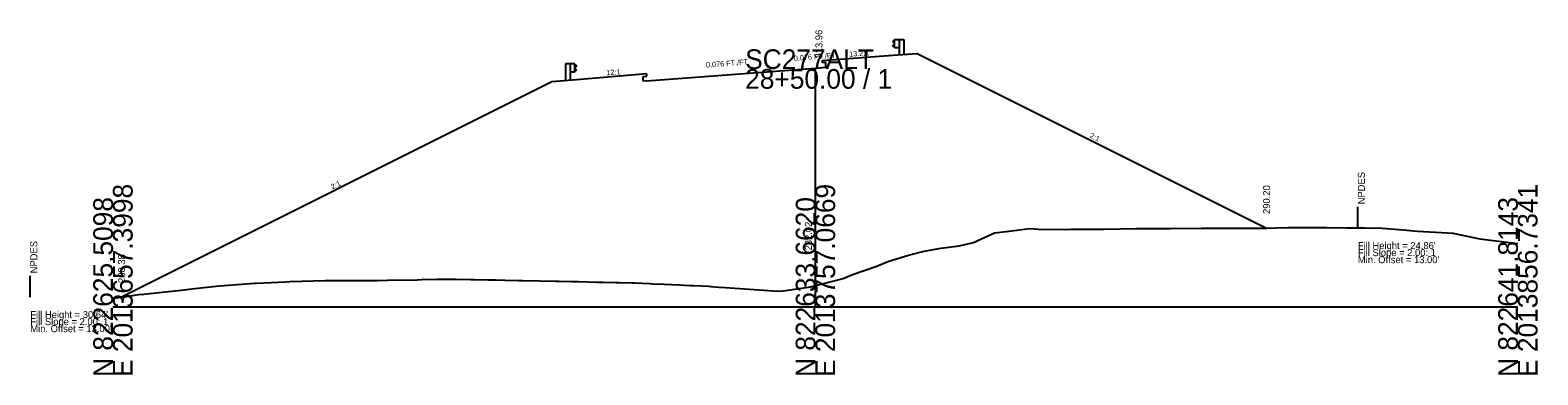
# Model space of a CAD drawing. Extents: x 205929 to 2357175, y -1785700 to 827636.
# Drawn here: x 2017408.4 to 2017623, y 826534.6 to 826583.6 of the extents above; entities that cross this region are included whole.
import ezdxf

# ---------------------------------------------------------------- set-up
doc = ezdxf.new("R2010")
doc.units = 0
for name, color, linetype in [('RD_GPK_XS_Cell', 7, 'Continuous'), ('RD_XS_Base', 7, 'Continuous'), ('RD_XS_EarthShd', 7, 'Continuous'), ('RD_XS_ExGround', 7, 'Continuous'), ('RD_XS_GR', 7, 'Continuous'), ('RD_XS_NPDES', 7, 'Continuous'), ('RD_XS_Pave', 7, 'Continuous'), ('RD_XS_TieSlope', 7, 'Continuous'), ('RD_XS_TX_Elev_EX', 7, 'Continuous'), ('RD_XS_TX_Elev_PR', 7, 'Continuous'), ('RD_XS_TX_ShdSlope', 7, 'Continuous'), ('RD_XS_TX_Slope', 7, 'Continuous'), ('RD_XS_TX_Warning', 7, 'Continuous')]:
    doc.layers.add(name, color=color, linetype=linetype)

msp = doc.modelspace()

# ---------------------------------------------------------------- linework, layer by layer
at = {"layer": 'RD_GPK_XS_Cell'}
for p, q in [((2017520.17, 826544.26), (2017520.17, 826578.09)), ((2017420.17, 826544.26), (2017520.17, 826544.26)), ((2017520.17, 826544.26), (2017620.17, 826544.26))]:
    msp.add_line(p, q, dxfattribs=at)
at = {"layer": 'RD_XS_Base'}
for p, q in [((2017496.17, 826576.4), (2017520.17, 826578.22)), ((2017520.17, 826578.22), (2017521.17, 826578.3))]:
    msp.add_line(p, q, dxfattribs=at)
at = {"layer": 'RD_XS_EarthShd'}
for p, q in [((2017521.17, 826579.3), (2017531.17, 826580.06)), ((2017531.17, 826580.06), (2017534.67, 826580.32)), ((2017496.17, 826577.4), (2017486.17, 826576.57)), ((2017486.17, 826576.57), (2017482.67, 826576.28))]:
    msp.add_line(p, q, dxfattribs=at)
at = {"layer": 'RD_XS_ExGround'}
msp.add_lwpolyline([(2017420.17, 826545.51), (2017420.29, 826545.5), (2017422.14, 826545.73), (2017423.25, 826545.89), (2017423.87, 826546), (2017424.55, 826546.06), (2017426.74, 826546.29), (2017430.29, 826546.68), (2017431.38, 826546.8), (2017435.3, 826547.23), (2017436.01, 826547.29), (2017440.32, 826547.6), (2017440.65, 826547.62), (2017444.71, 826547.81), (2017445.39, 826547.84), (2017450.35, 826547.97), (2017450.86, 826547.99), (2017455.37, 826548), (2017457.08, 826548), (2017457.8, 826548.01), (2017459.23, 826548.03), (2017463.48, 826548.11), (2017464.09, 826548.12), (2017466.28, 826548.16), (2017468.23, 826548.18), (2017468.62, 826548.19), (2017469.05, 826548.19), (2017471.08, 826548.15), (2017471.62, 826548.14), (2017473.55, 826548.09), (2017474.74, 826548.07), (2017476.02, 826548.04), (2017477.87, 826548.01), (2017478.5, 826548), (2017480.91, 826547.95), (2017483.22, 826547.9), (2017483.69, 826547.89), (2017485.46, 826547.85), (2017486.39, 826547.83), (2017487.72, 826547.8), (2017489.09, 826547.77), (2017489.94, 826547.76), (2017491.8, 826547.71), (2017492.2, 826547.7), (2017494.15, 826547.66), (2017494.48, 826547.64), (2017496.54, 826547.55), (2017497.09, 826547.53), (2017498.64, 826547.46), (2017499.69, 826547.41), (2017500.76, 826547.36), (2017502.29, 826547.3), (2017502.86, 826547.27), (2017504.97, 826547.17), (2017505.32, 826547.15), (2017506.4, 826547.05), (2017507.35, 826546.98), (2017508.05, 826546.94), (2017514.85, 826546.48), (2017515.57, 826546.5), (2017519.49, 826547.09), (2017520.17, 826547.27), (2017520.59, 826547.39), (2017524.12, 826548.27), (2017525.6, 826548.88), (2017528.76, 826549.99), (2017530.62, 826550.72), (2017533.4, 826551.6), (2017535.64, 826552.15), (2017538.04, 826552.6), (2017540.65, 826552.94), (2017542.67, 826553.38), (2017545.67, 826554.77), (2017547.31, 826554.98), (2017550.69, 826555.38), (2017551.95, 826555.3), (2017555.7, 826555.27), (2017556.59, 826555.28), (2017560.72, 826555.32), (2017561.22, 826555.32), (2017565.86, 826555.37), (2017567.37, 826555.38), (2017570.75, 826555.41), (2017575.14, 826555.42), (2017575.77, 826555.43), (2017579.77, 826555.43), (2017580.79, 826555.45), (2017584.41, 826555.46), (2017585.8, 826555.49), (2017587.45, 826555.52), (2017590.82, 826555.53), (2017592.91, 826555.53), (2017595.84, 826555.47), (2017598.37, 826555.47), (2017600.85, 826555.44), (2017603.84, 826555.19), (2017605.87, 826555), (2017609.3, 826554.84), (2017610.89, 826554.74), (2017614.76, 826553.9), (2017615.9, 826553.8), (2017620.17, 826553.26)], dxfattribs=at)
at = {"layer": 'RD_XS_GR'}
for p, q in [((2017531.44, 826582.23), (2017531.17, 826582.03)), ((2017531.17, 826582.03), (2017531.17, 826581.98)), ((2017531.17, 826581.98), (2017531.44, 826581.78)), ((2017531.17, 826581.46), (2017531.44, 826581.66)), ((2017531.17, 826581.41), (2017531.17, 826581.46)), ((2017531.44, 826581.14), (2017531.44, 826582.31)), ((2017531.44, 826582.31), (2017532.11, 826582.31)), ((2017532.11, 826582.31), (2017532.11, 826580.13)), ((2017532.11, 826582.31), (2017532.78, 826582.31)), ((2017532.78, 826582.31), (2017532.78, 826580.18)), ((2017531.44, 826581.21), (2017531.17, 826581.41)), ((2017531.44, 826581.14), (2017532.11, 826581.14)), ((2017484.57, 826578.82), (2017484.57, 826576.44)), ((2017485.24, 826578.82), (2017484.57, 826578.82)), ((2017485.24, 826578.82), (2017485.24, 826576.49)), ((2017485.9, 826578.82), (2017485.24, 826578.82)), ((2017485.9, 826577.65), (2017485.24, 826577.65)), ((2017485.9, 826577.65), (2017485.9, 826578.82)), ((2017485.9, 826578.75), (2017486.17, 826578.55)), ((2017486.17, 826578.5), (2017485.9, 826578.3)), ((2017486.17, 826577.97), (2017485.9, 826578.17)), ((2017485.9, 826577.72), (2017486.17, 826577.92)), ((2017486.17, 826578.55), (2017486.17, 826578.5)), ((2017486.17, 826577.92), (2017486.17, 826577.97))]:
    msp.add_line(p, q, dxfattribs=at)
at = {"layer": 'RD_XS_NPDES'}
for p, q in [((2017597.39, 826555.46), (2017597.39, 826558.46)), ((2017408.4, 826545.64), (2017408.4, 826548.64))]:
    msp.add_line(p, q, dxfattribs=at)
at = {"layer": 'RD_XS_Pave'}
for p, q in [((2017496.17, 826577.07), (2017496.17, 826577.4)), ((2017521.17, 826578.97), (2017521.17, 826579.3)), ((2017521.67, 826579.01), (2017521.17, 826578.97)), ((2017521.17, 826578.3), (2017521.67, 826578.34)), ((2017521.67, 826578.34), (2017521.67, 826579.01)), ((2017495.67, 826577.03), (2017496.17, 826577.07)), ((2017495.67, 826576.36), (2017495.67, 826577.03)), ((2017496.17, 826576.4), (2017495.67, 826576.36))]:
    msp.add_line(p, q, dxfattribs=at)
at = {"layer": 'RD_XS_TieSlope'}
for p, q in [((2017534.67, 826580.32), (2017584.39, 826555.46)), ((2017482.67, 826576.28), (2017421.4, 826545.64))]:
    msp.add_line(p, q, dxfattribs=at)

# ---------------------------------------------------------------- texts
at = {"layer": 'RD_GPK_XS_Cell'}
for s, p in [('SC277ALT', (2017510.17, 826578.09)), ('28+50.00 / 1', (2017510.17, 826575.29))]:
    msp.add_text(s, height=2.8, dxfattribs=at).set_placement(p)
for s, p in [('E 2013657.3998', (2017422.97, 826534.26)), ('E 2013757.0669', (2017522.97, 826534.26)), ('E 2013856.7341', (2017622.97, 826534.26)), ('N 822625.5098', (2017420.17, 826534.26)), ('N 822633.6620', (2017520.17, 826534.26)), ('N 822641.8143', (2017620.17, 826534.26))]:
    msp.add_text(s, height=2.8, rotation=90, dxfattribs=at).set_placement(p)
at = {"layer": 'RD_XS_TX_Elev_EX'}
msp.add_text('282.02', height=1, rotation=90, dxfattribs=at).set_placement((2017519.67, 826552.27))
at = {"layer": 'RD_XS_TX_Elev_PR'}
for s, p in [(' 313.96', (2017521.17, 826579.22)), ('290.20', (2017584.89, 826557.46)), ('280.38', (2017421.9, 826547.64))]:
    msp.add_text(s, height=1, rotation=90, dxfattribs=at).set_placement(p)
at = {"layer": 'RD_XS_TX_ShdSlope'}
for s, rotation, p in [('13.2:1', 4.3347, (2017525, 826579.84)), ('12:1', 4.7636, (2017490.44, 826577.18))]:
    msp.add_text(s, height=0.75, rotation=rotation, dxfattribs=at).set_placement(p)
at = {"layer": 'RD_XS_TX_Slope'}
for s, rotation, p in [('0.076 FT./FT.', 4.3347, (2017504.62, 826578.29)), ('0.076 FT./FT.', 4.3347, (2017517.12, 826579.24)), ('2:1', 333.4349, (2017559.14, 826568.37)), ('2:1', 26.5651, (2017451.42, 826560.93))]:
    msp.add_text(s, height=0.75, rotation=rotation, dxfattribs=at).set_placement(p)
at = {"layer": 'RD_XS_TX_Warning'}
for p in [(2017598.39, 826558.46), (2017409.4, 826548.64)]:
    msp.add_text(' NPDES', height=1, rotation=90, dxfattribs=at).set_placement(p)
for s, p in [("Fill Height = 24.86' ", (2017597.39, 826552.46)), ('Fill Slope = 2.00: 1', (2017597.39, 826551.46)), ("Min. Offset = 13.00' ", (2017597.39, 826550.46)), ("Fill Height = 30.64' ", (2017408.4, 826542.64)), ('Fill Slope = 2.00: 1', (2017408.4, 826541.64)), ("Min. Offset = 13.00' ", (2017408.4, 826540.64))]:
    msp.add_text(s, height=1, dxfattribs=at).set_placement(p)

doc.saveas('drawing.dxf')
